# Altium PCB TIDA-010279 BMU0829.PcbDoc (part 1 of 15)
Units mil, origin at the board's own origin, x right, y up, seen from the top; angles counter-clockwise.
Board outline 11269.69 x 4438.98 mil, 4 copper layers (Top Layer, Signal Layer 1, Signal Layer 2, Bottom Layer), stack 61.6 mil thick; 1494 components, 725 nets, 3766 pads, 2728 vias.
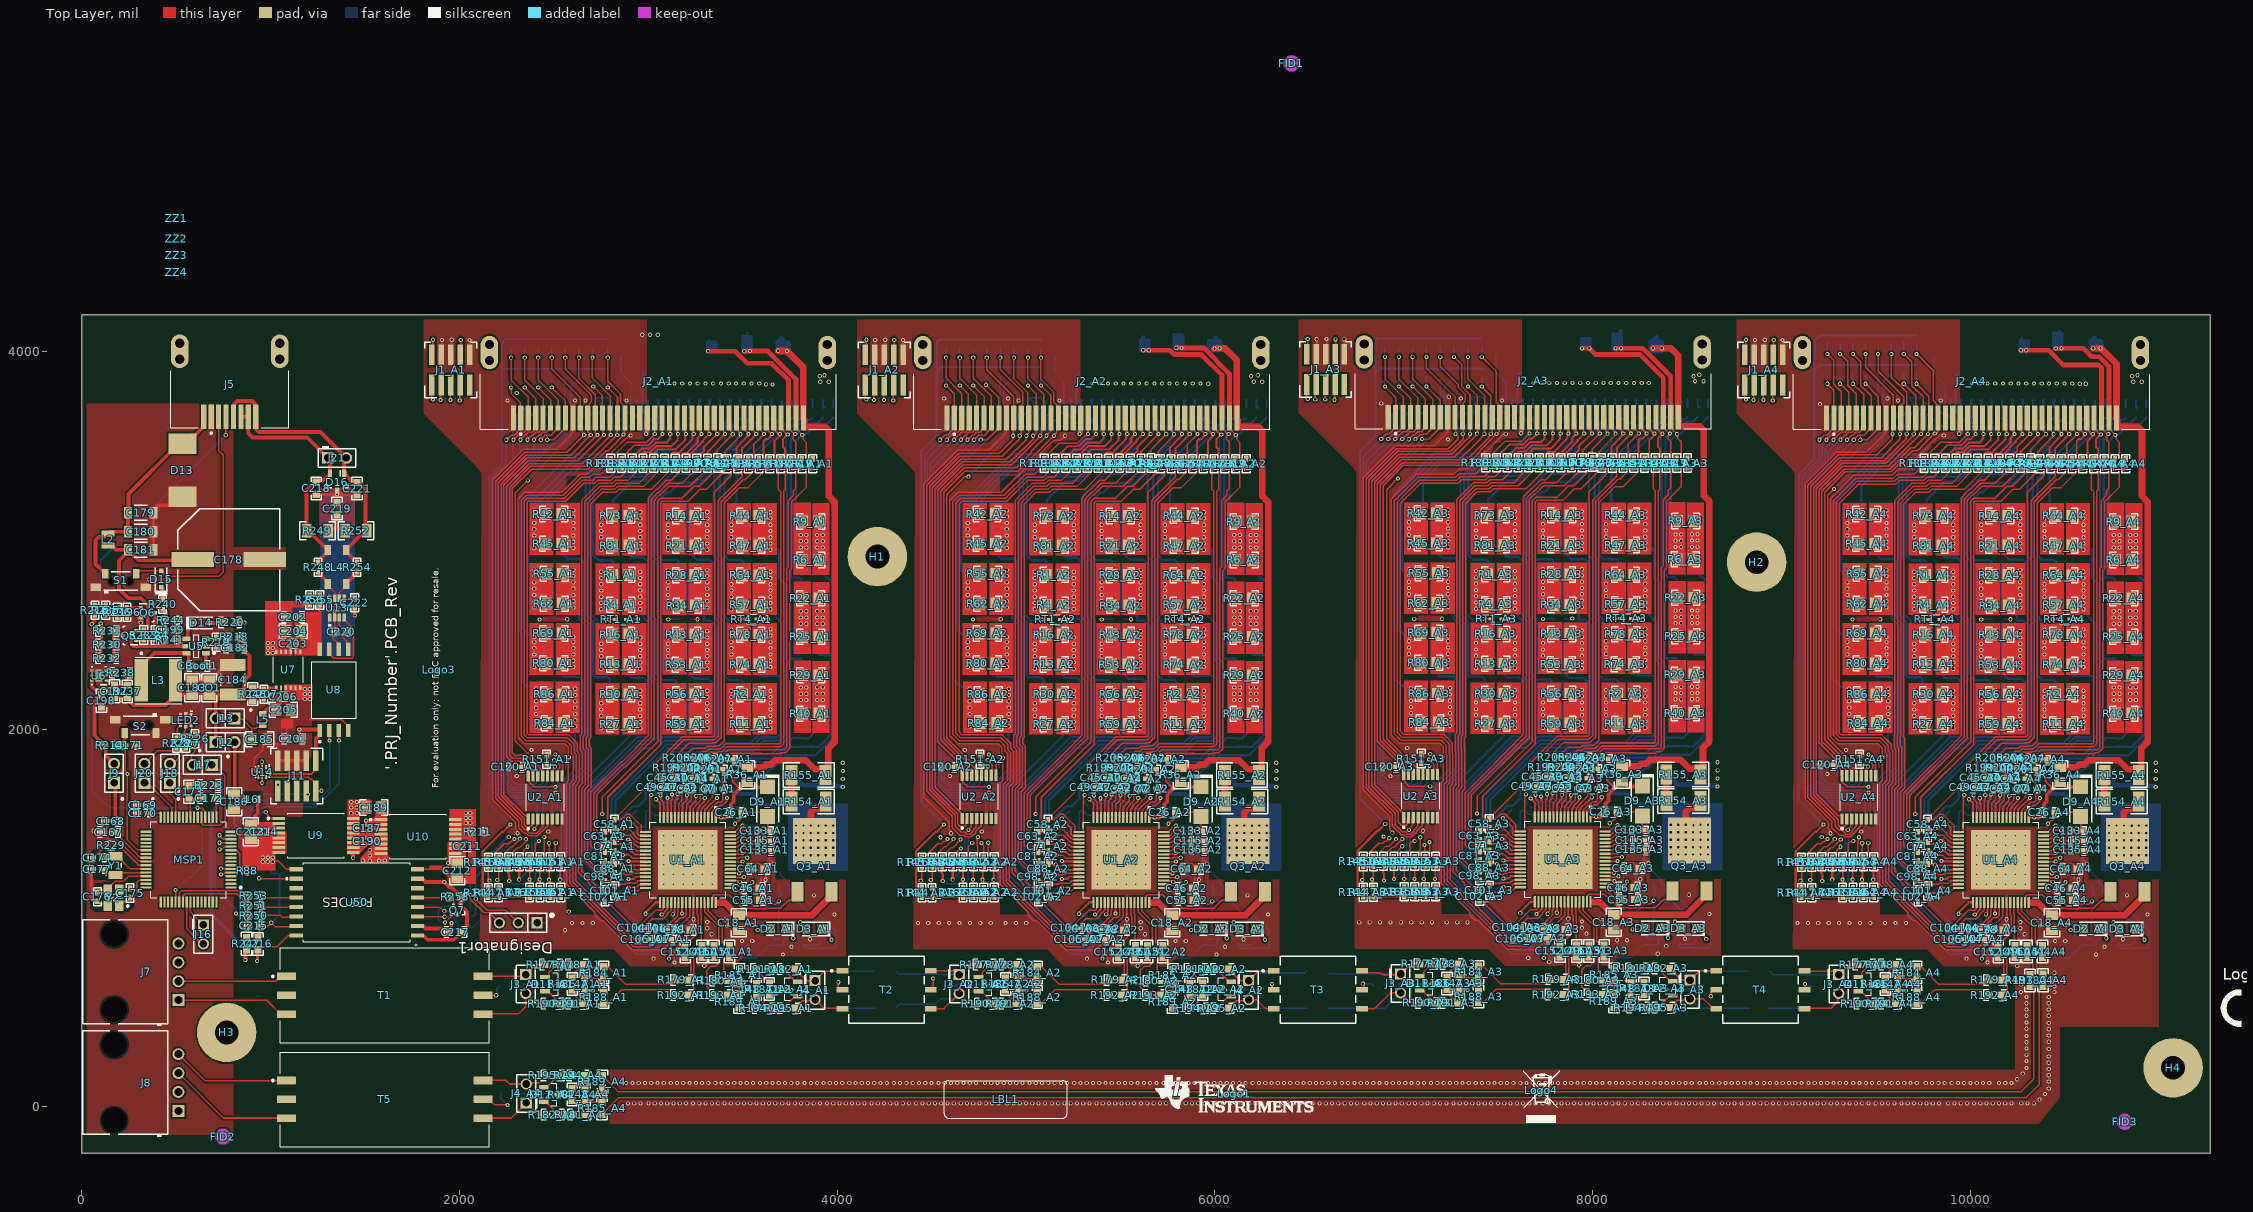
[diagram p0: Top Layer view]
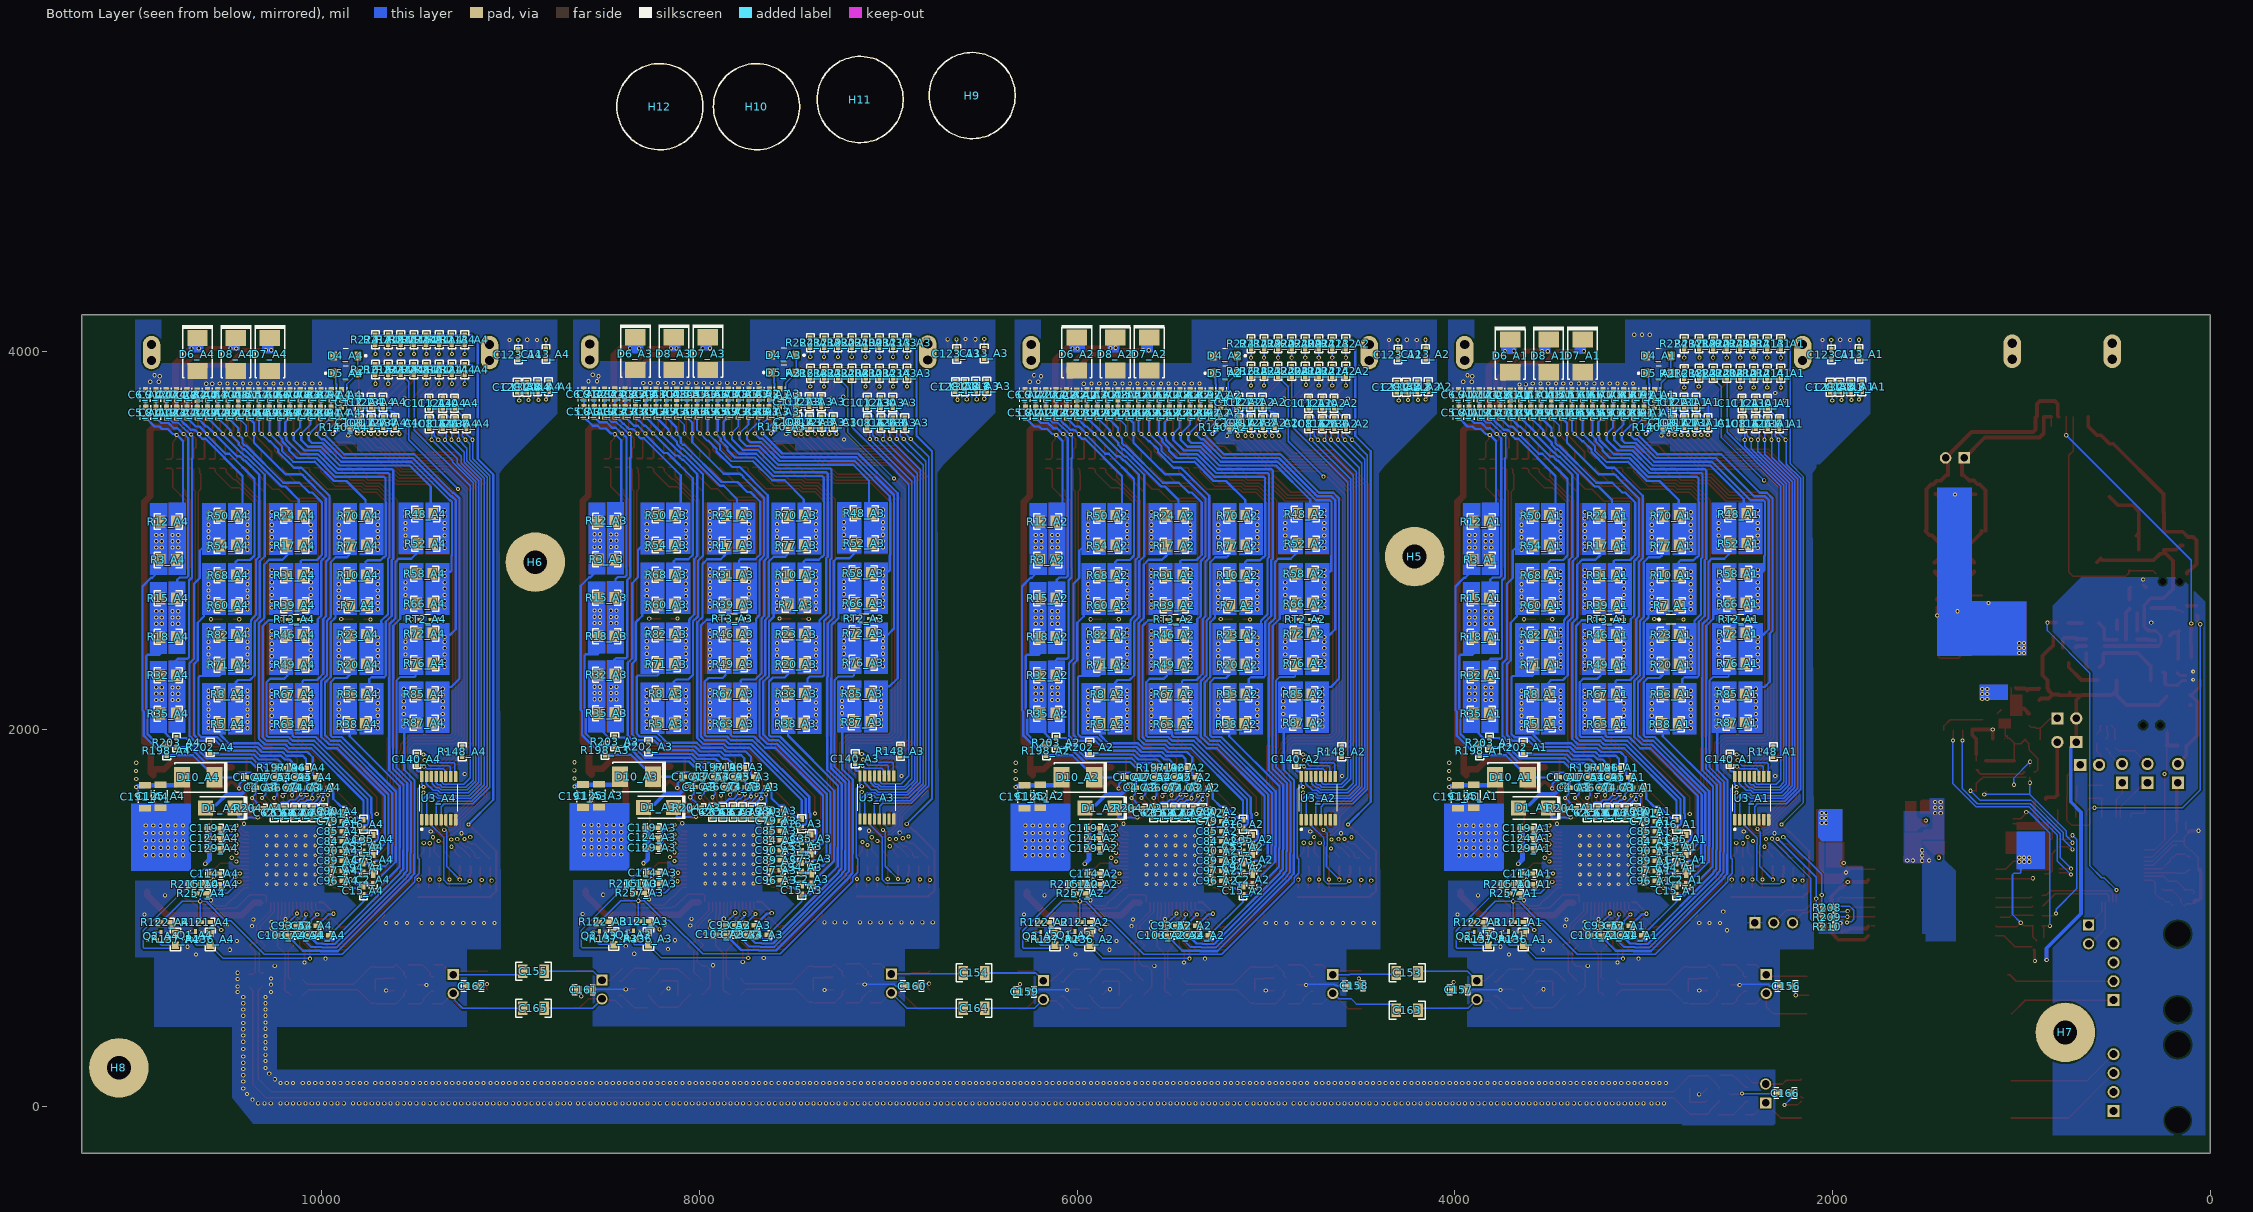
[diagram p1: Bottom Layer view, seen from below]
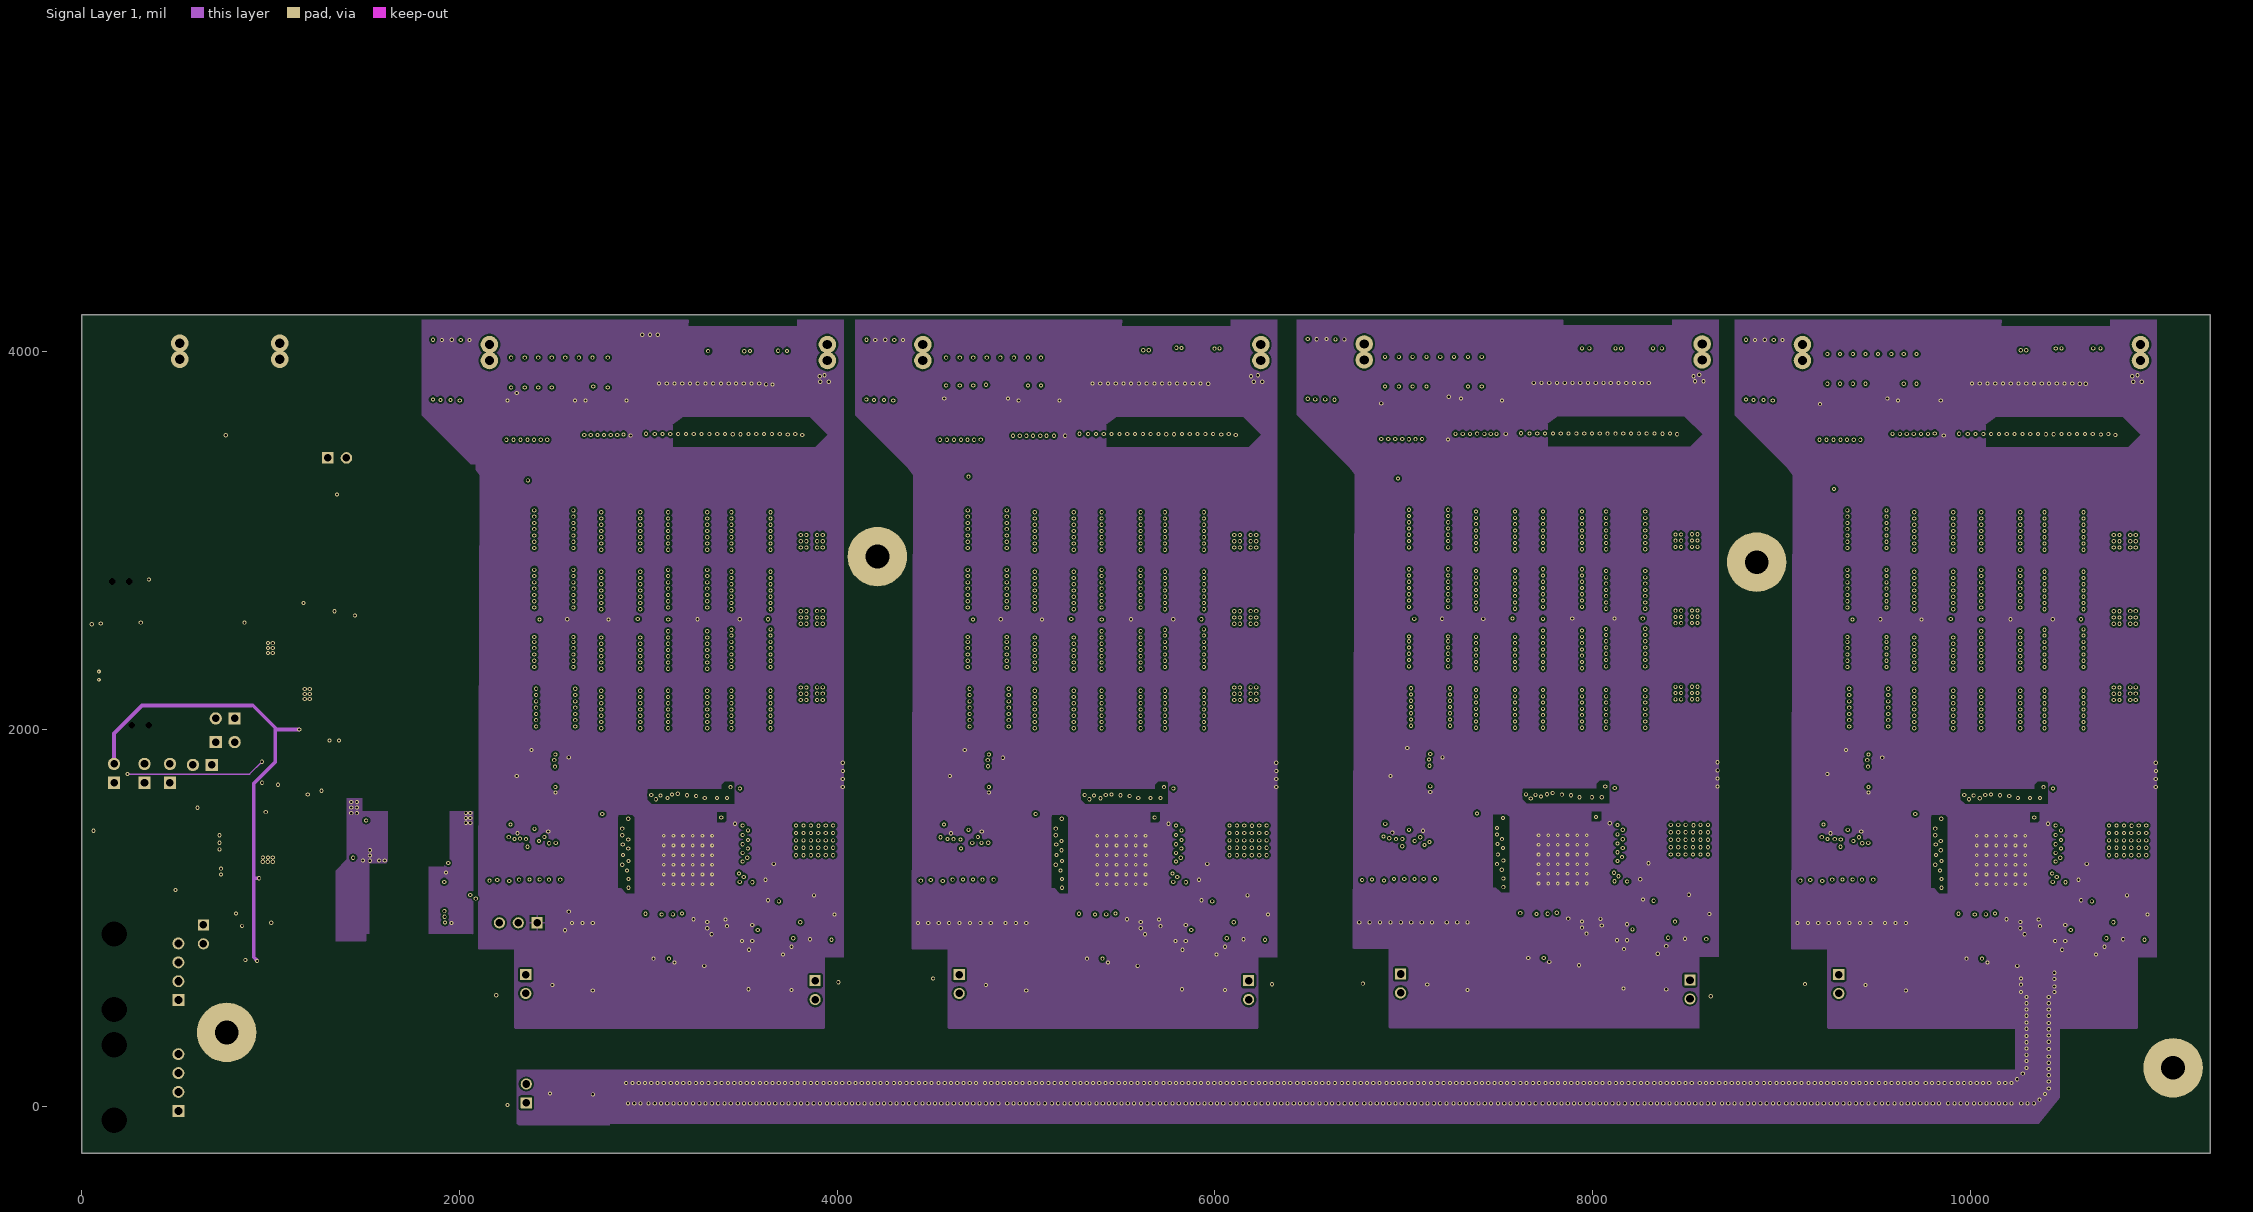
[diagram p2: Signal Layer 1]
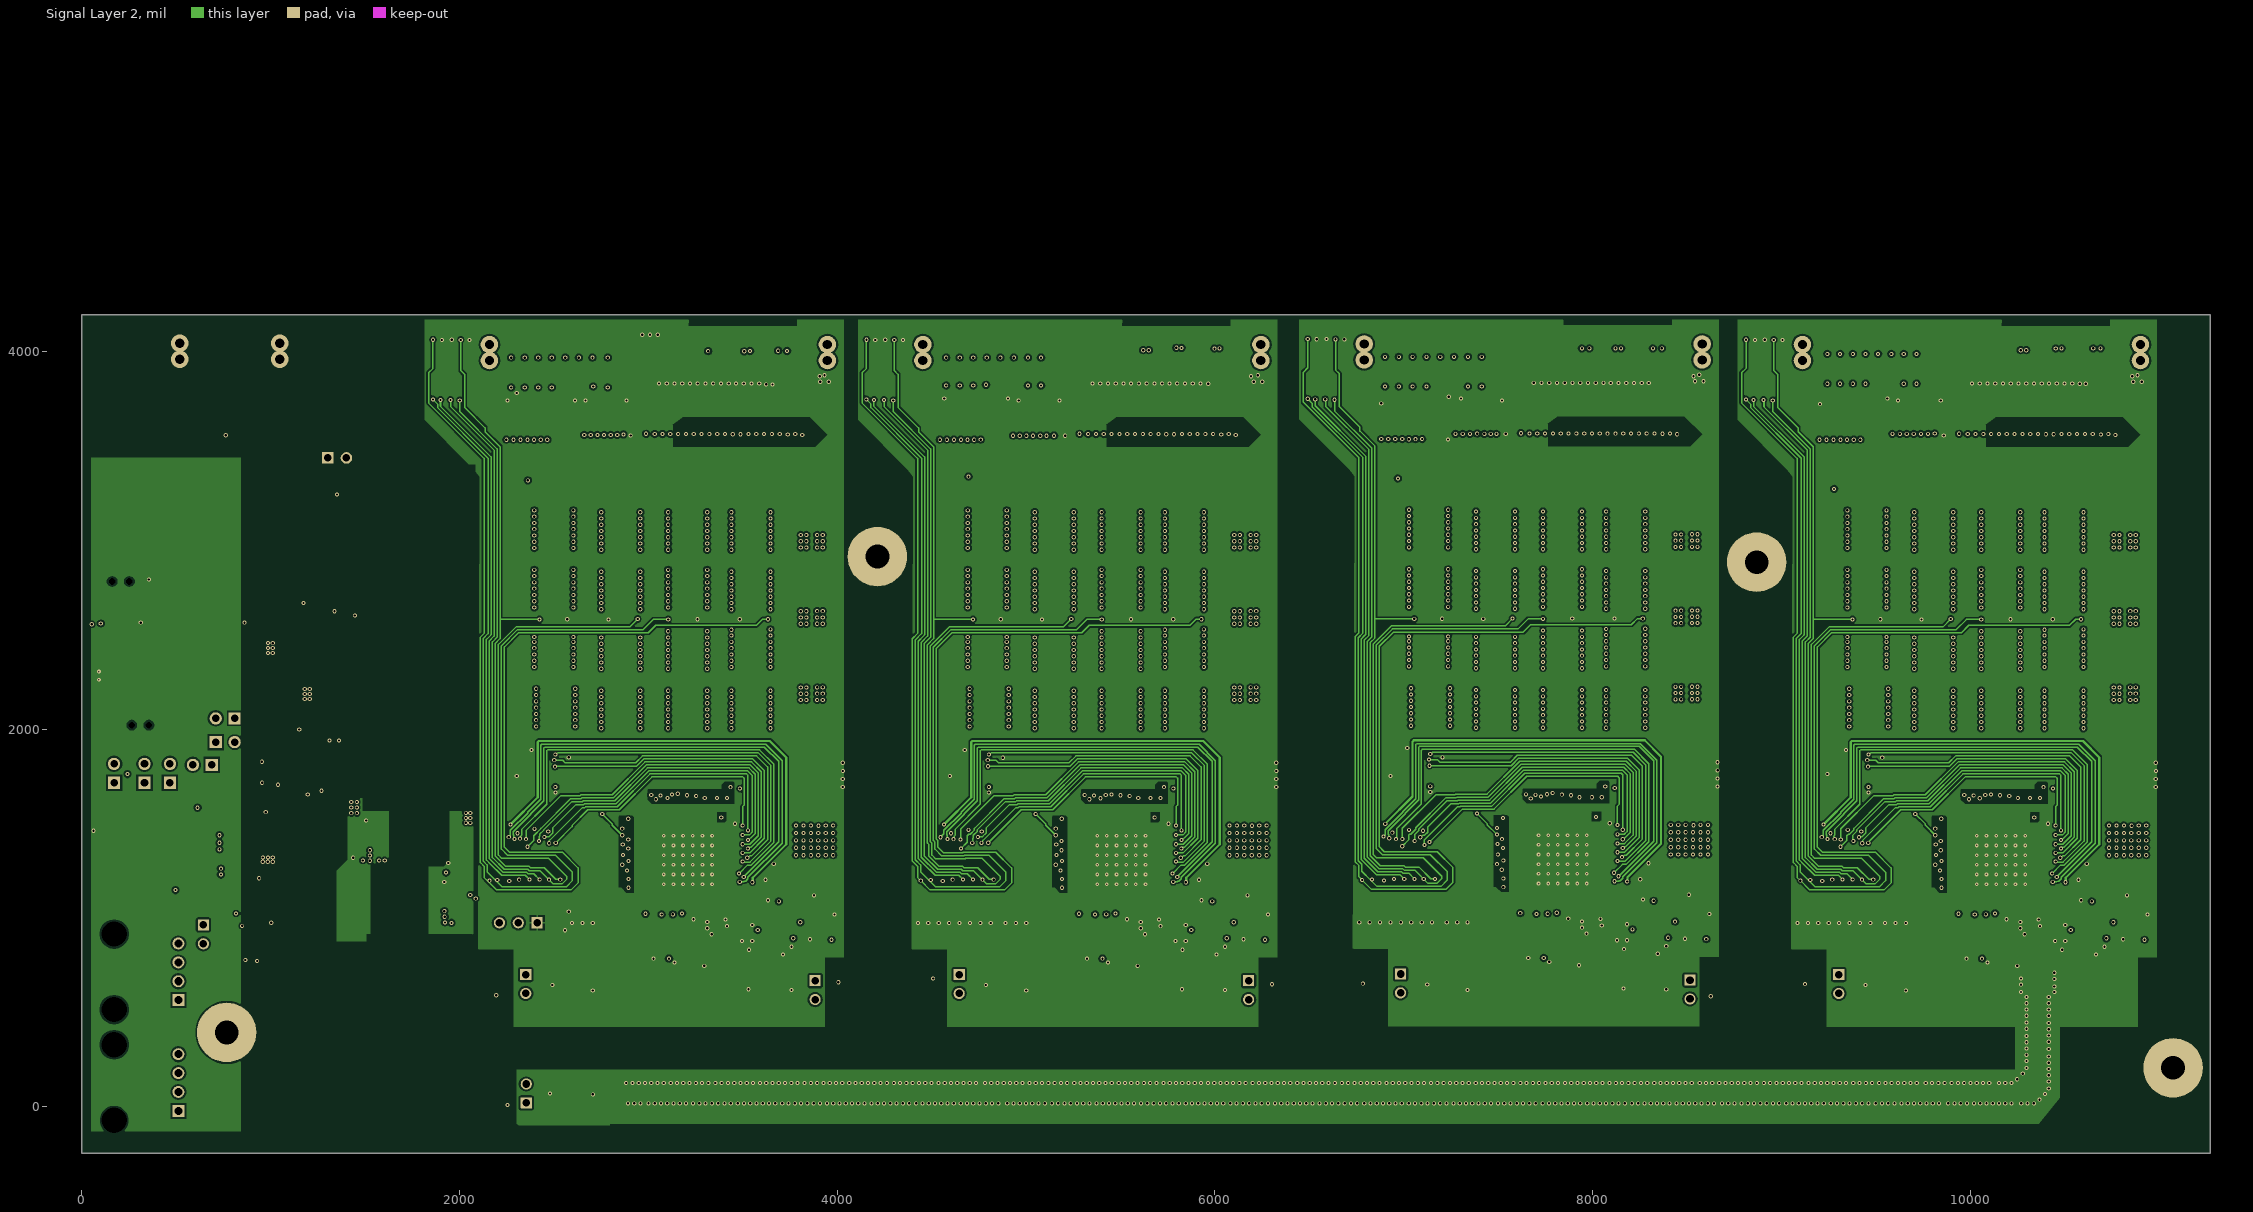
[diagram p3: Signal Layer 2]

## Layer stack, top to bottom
Top Solder: solder mask 0.4, Solder Resist, Dk 3.5
Top Layer: signal copper 2.8
Dielectric 1: prepreg 8, FR-4 High Tg, Dk 4.2
Signal Layer 1: signal copper 1.4
Dielectric 2: core 37.2, FR-4 High Tg, Dk 4.2
Signal Layer 2: signal copper 1.4
Dielectric 3: prepreg 8, FR-4 High Tg, Dk 4.2
Bottom Layer: signal copper 2.8
Bottom Solder: solder mask 0.4, Solder Resist, Dk 3.5

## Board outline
0,-246.06 11269.69,-246.06 11269.68,4192.91 0,4192.91

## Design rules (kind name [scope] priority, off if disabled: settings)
AcuteAngle [All] p1: minimum=4.50000000000000E+0001 checktracksonly=FALSE
AssemblyTestPointUsage [All] p1: valid=2
BoardOutlineClearance BoardOutlineClearance_MountingHoles [OnCopper and InComponentClass('Mounting Holes')] p1: gap=39.37 ignorepadtopadclearanceinfootprint=FALSE
BoardOutlineClearance BoardOutlineClearance_Poly [OnCopper and IsPoly] p2: gap=25 ignorepadtopadclearanceinfootprint=FALSE
BoardOutlineClearance [OnCopper and Not InComponentClass('Logo') and not InComponentClass('FiducialMark') and not InRegion(1000,500,4000,800) and not InPoly] p3: gap=40 ignorepadtopadclearanceinfootprint=FALSE
Clearance Clearance_Keepouts [((IsTrack Or IsArc) And Not InPoly) And IsFree and IsKeepOut vs ((IsTrack Or IsArc) And Not InPoly) And IsFree and IsKeepOut] p1: gap=0 ignorepadtopadclearanceinfootprint=FALSE
Clearance Clearance_Poly [InPolygon] p2: gap=10 ignorepadtopadclearanceinfootprint=TRUE
Clearance Clearance_FiducialMark [IsKeepOut and InComponentClass('FiducialMark') vs IsPad and InComponentClass('FiducialMark')] p3: gap=0 ignorepadtopadclearanceinfootprint=FALSE
Clearance [All] p4: gap=7.87 ignorepadtopadclearanceinfootprint=TRUE
ComponentClearance ComponentClearance_MountingHoles_FiducialMarks [InComponentClass('Mounting Holes') vs InComponentClass('FiducialMark')] p1: gap=50 collisioncheckmode=3 verticalgap=10 showdistances=FALSE
ComponentClearance ComponentClearance_Shunt [InComponentClass('Header') vs InComponentClass('Shunt')] p2: gap=0 collisioncheckmode=3 verticalgap=0 showdistances=FALSE
ComponentClearance ComponentClearance_Logo [InComponentClass('Logo')] p3: gap=30 collisioncheckmode=3 verticalgap=10 showdistances=FALSE
ComponentClearance ComponentClearance_ScrewToNut [(HasFootprint('NY PMS 440 0025 PH')) vs (HasFootprint('Keystone_1902C'))] p4: gap=5 collisioncheckmode=3 verticalgap=10 showdistances=FALSE
ComponentClearance ComponentClearance_MountingHoles [InComponentClass('Mounting Holes')] p5: gap=100 collisioncheckmode=3 verticalgap=100000 showdistances=FALSE
ComponentClearance ComponentClearance_SmallPassives [HasFootprint('0201*') or HasFootprint('0402*') or HasFootprint('0508') or HasFootprint('0603*') or HasFootprint('0612') or HasFootprint('0805*') or HasFootprint('0815*') or HasFootprint('0830*') or HasFootprint('1206*') or HasFootprint('1210*') or HasFootprint('1808*') or HasFootprint('1812*') or HasFootprint('1825*') or HasFootprint('2010*') or HasFootprint('2220*') or HasFootprint('2225*') or HasFootprint('2512*') or HasFootprint('2728*') or HasFootprint('3518*') vs HasFootprint('0201*') or HasFootprint('0402*') or HasFootprint('0508') or HasFootprint('0603*') or HasFootprint('0612') or HasFootprint('0805*') or HasFootprint('0815*') or HasFootprint('0830*') or HasFootprint('1206*') or HasFootprint('1210*') or HasFootprint('1808*') or HasFootprint('1812*') or HasFootprint('1825*') or HasFootprint('2010*') or HasFootprint('2220*') or HasFootprint('2225*') or HasFootprint('2512*') or HasFootprint('2728*') or HasFootprint('3518*')] p6: gap=14.96 collisioncheckmode=3 verticalgap=10 showdistances=FALSE
ComponentClearance ComponentClearance_THtoSMT [IsThruComponent vs IsSMTComponent] p7: gap=30 collisioncheckmode=3 verticalgap=30 showdistances=FALSE
ComponentClearance ComponentClearance_THtoTH [IsThruComponent vs IsThruComponent] p8: gap=20 collisioncheckmode=3 verticalgap=30 showdistances=FALSE
ComponentClearance [All] p9: gap=20 collisioncheckmode=3 verticalgap=10 showdistances=FALSE
DiffPairsRouting [All] p1: maxlimit=100 minlimit=10 mostfreqgap=10 toplayer_minwidth=15 toplayer_maxwidth=15 toplayer_prefwidth=15 midlayer1_minwidth=15 midlayer1_maxwidth=15 midlayer1_prefwidth=15 midlayer2_minwidth=15 midlayer2_maxwidth=15 midlayer2_prefwidth=15 bottomlayer_minwidth=15 bottomlayer_maxwidth=15 bottomlayer_prefwidth=15 maxuncoupledlength=1000
FabricationTestPointUsage TestPointUsage [All] p1: valid=2 allowmultiple=FALSE
FabricationTestpoint Testpoint [All] p1: side=3 testpointundercomponent=TRUE minsize=40 maxsize=100 preferedsize=60 minholesize=0 maxholesize=40 preferedholesize=32 testpointgrid=1 allowsidetop=TRUE allowsidebottom=TRUE usegrid=TRUE gridtolerance=0.01
FanoutControl Fanout_LCC [IsLCC] p1: bgadir=Out bgaviamode=Centered fanoutstyle=Auto fanoutdirection=Alternating viagrid=1 // Fanout_LCC (Default Rule)
FanoutControl Fanout_BGA [IsBGA] p2: bgadir=Out bgaviamode=Centered fanoutstyle=Auto fanoutdirection=Alternating viagrid=1 // Fanout_BGA (Default Rule)
FanoutControl Fanout_Default [All] p4: bgadir=Out bgaviamode=Centered fanoutstyle=Auto fanoutdirection=Alternating viagrid=1 // Fanout_Default (Default Rule)
FanoutControl Fanout_Small [(CompPinCount < 5)] p5: bgadir=Out bgaviamode=Centered fanoutstyle=Auto fanoutdirection=OutThenIn viagrid=1 // Fanout_Small (Default Rule)
HoleSize [All] p1: absolutevalues=TRUE maxlimit=251 minlimit=7.87 maxpercent=80.000 minpercent=20.000
MinimumAnnularRing MinimumAnnularRing_ThermalPadVias [IsVia and InAnyComponent] p1: minimumring=5.91
MinimumAnnularRing [All] p2: minimumring=5
MinimumSolderMaskSliver MinimumSolderMaskSliver_Logo [InComponentClass('Logo') vs InComponentClass('Logo')] p1: minsoldermaskwidth=0.7
MinimumSolderMaskSliver [All] p2: minsoldermaskwidth=3.94
PlaneConnect [All] p1: planeconnectstyle=Relief reliefexpansion=10 reliefentries=4 reliefconductorwidth=10 reliefairgap=10
PolygonConnect [All] p1: thpad.connectstyle=Relief thpad.reliefconductorwidth=10 thpad.reliefentries=4 thpad.polygonreliefangle="90 Angle" thpad.airgapwidth=10 smdpad.connectstyle=Direct smdpad.reliefconductorwidth=10 smdpad.reliefentries=4 smdpad.polygonreliefangle="90 Angle" smdpad.airgapwidth=10 via.connectstyle=Direct via.reliefconductorwidth=10 via.reliefentries=4 via.polygonreliefangle="90 Angle" via.airgapwidth=10
RoomDefinition [InComponentClass('Room Definition3')] p1: confinementstyle=ConfineIn formatcopy=TRUE lockcomponents=FALSE outline 1788.32,393.7 4074.8,393.7 4074.8,4320.87 1788.32,4320.87
RoomDefinition RoomDefinition_1 [InComponentClass('Room Definition6') vs False] p2: confinementstyle=ConfineIn formatcopy=TRUE lockcomponents=FALSE outline 4083.33,393.7 6369.82,393.7 6369.82,4320.87 4083.33,4320.87
RoomDefinition RoomDefinition_2 [InComponentClass('Room Definition7') vs False] p3: confinementstyle=ConfineIn formatcopy=TRUE lockcomponents=FALSE outline 6419.93,396.91 8706.42,396.91 8706.42,4324.07 6419.93,4324.07
RoomDefinition RoomDefinition_3 [InComponentClass('Room Definition8') vs False] p4 off: confinementstyle=ConfineIn formatcopy=TRUE lockcomponents=FALSE outline 8740.16,393.7 11026.65,393.7 11026.65,4320.87 8740.16,4320.87
RoutingVias ThermalPadVias [IsVia and InAnyComponent] p1: holewidth=7.87 width=19.68 viastyle="Through Hole" minholewidth=7.87 minwidth=19.68 maxholewidth=50 maxwidth=93
RoutingVias [All] p2: holewidth=16 width=34 viastyle="Through Hole" minholewidth=7.8 minwidth=22 maxholewidth=50 maxwidth=93
SilkToBoardRegionClearance [Not ((IsComment or IsDesignator) And (Hide <> 'False')) and not InRegion(1000,500,4000,800)] p1:
SilkToSilkClearance SilkToSilkClearance_Pb-FreeLogo [(HasFootprint('Pb-Free_Overlay_Medium') OR HasFootprint('Pb-Free_Overlay_Small')) vs (HasFootprint('Pb-Free_Overlay_Medium') OR HasFootprint('Pb-Free_Overlay_Small'))] p1: silktosilkclearance=0
SilkToSilkClearance [All] p2: silktosilkclearance=3.94
SilkToSolderMaskClearance SilkToComponentPadClearance [(IsPad or IsFill or IsRegion) and InAnycomponent] p1: minsilkscreentomaskgap=3 clearancetoexposedcopper=TRUE
SilkToSolderMaskClearance "Silk to Solder Mask Opening" [All] p2: minsilkscreentomaskgap=3.94 clearancetoexposedcopper=FALSE
SolderMaskExpansion [All] p1: expansion=1.97 istentingtop=FALSE
UnRoutedNet [All] p1: checkbadconnections=TRUE
Width [All] p1: maxlimit=100 minlimit=6 preferedwidth=8 checkconnectedcopper=TRUE
14 further rules are at their usual default settings.

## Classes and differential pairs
component class MCU0: C167 C168 C169 C170 C171 C172 C173 C174 C175 C176 C177 C178 C179 C180 C181 C182 C183 C184 C185 C186 C187 C189 C190 C196 C197 C198 C199 C201 C202 C203 C204 C205 C206 C207 C211 C212 C213 C214 C215 C216 C217 C218 C219 C220 C221 C222 CBoot1 CO1 D13 D14 D15 D16 J9 J11 J12 J13 J16 J17 J18 J20 J21 L2 L3 L4 L5 L6 LED2 MSP1 Q5 Q6 Q7 R88 R214 R216 R218 R219 R220 R223 R226 R227 R228 R229 R230 R231 R232 R233 R234 R235 R236 R237 R238 R240 R241 R244 R246 R247 R248 R249 R250 R251 R252 R253 R254 R255 R256 R258 S2 U5 U6 U7 U8 U9 U10 U13 U14 U50 Y1 Y2
component class Header: J3_A1 J3_A2 J3_A3 J3_A4 J4_A1 J4_A2 J4_A3 J4_A4 J9 J12 J13 J16 J17 J18 J20
component class "Mounting Holes": H1 H2 H3 H4
component class Logo: Logo1
component class FiducialMark: FID1 FID2 FID3
component class AssemblyNote: ZZ1 ZZ2 ZZ3 ZZ4
component class Label: LBL1

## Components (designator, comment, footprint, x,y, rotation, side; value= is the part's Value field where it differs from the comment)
C1_A1 "GCM155R71H104KE02D" 0402 3421.64,1744.01 r0 bottom value=0.1uF (schematic designator C1)
C1_A2 "GCM155R71H104KE02D" 0402 5716.65,1744.01 r0 bottom value=0.1uF (schematic designator C1)
C1_A3 "GCM155R71H104KE02D" 0402 8053.25,1747.22 r0 bottom value=0.1uF (schematic designator C1)
C1_A4 "GCM155R71H104KE02D" 0402 10373.48,1744.01 r0 bottom value=0.1uF (schematic designator C1)
C2_A1 "GCM155R71H104KE02D" 0402 2773.73,1202.94 r270 bottom value=0.1uF (schematic designator C2)
C2_A2 "GCM155R71H104KE02D" 0402 5068.74,1202.94 r270 bottom value=0.1uF (schematic designator C2)
C2_A3 "GCM155R71H104KE02D" 0402 7405.34,1206.15 r270 bottom value=0.1uF (schematic designator C2)
C2_A4 "GCM155R71H104KE02D" 0402 9725.57,1202.94 r270 bottom value=0.1uF (schematic designator C2)
C3_A1 "GCM155R71H104KE02D" 0402 3036.13,1690.14 r180 bottom value=0.1uF (schematic designator C3)
C3_A2 "GCM155R71H104KE02D" 0402 5331.15,1690.14 r180 bottom value=0.1uF (schematic designator C3)
C3_A3 "GCM155R71H104KE02D" 0402 7667.74,1693.35 r180 bottom value=0.1uF (schematic designator C3)
C3_A4 "GCM155R71H104KE02D" 0402 9987.97,1690.14 r180 bottom value=0.1uF (schematic designator C3)
C4_A1 "GCM155R71H104KE02D" 0402 3367,1690.14 r180 bottom value=0.1uF (schematic designator C4)
C4_A2 "GCM155R71H104KE02D" 0402 5662.01,1690.14 r180 bottom value=0.1uF (schematic designator C4)
C4_A3 "GCM155R71H104KE02D" 0402 7998.61,1693.35 r180 bottom value=0.1uF (schematic designator C4)
C4_A4 "GCM155R71H104KE02D" 0402 10318.84,1690.14 r180 bottom value=0.1uF (schematic designator C4)
C5_A1 "CGA3E2X7R2A223K080AA" FP-CGA3E2X7R2A223K080AA_0603-MFG 3978.41,3676.14 r90 bottom value=22nF (schematic designator C5)
C5_A2 "CGA3E2X7R2A223K080AA" FP-CGA3E2X7R2A223K080AA_0603-MFG 6273.43,3676.14 r90 bottom value=22nF (schematic designator C5)
C5_A3 "CGA3E2X7R2A223K080AA" FP-CGA3E2X7R2A223K080AA_0603-MFG 8610.03,3679.34 r90 bottom value=22nF (schematic designator C5)
C5_A4 "CGA3E2X7R2A223K080AA" FP-CGA3E2X7R2A223K080AA_0603-MFG 10930.26,3676.14 r90 bottom value=22nF (schematic designator C5)
C6_A1 "CGA3E2X7R2A223K080AA" FP-CGA3E2X7R2A223K080AA_0603-MFG 3979.76,3769.17 r90 bottom value=22nF (schematic designator C6)
C6_A2 "CGA3E2X7R2A223K080AA" FP-CGA3E2X7R2A223K080AA_0603-MFG 6274.77,3769.17 r90 bottom value=22nF (schematic designator C6)
C6_A3 "CGA3E2X7R2A223K080AA" FP-CGA3E2X7R2A223K080AA_0603-MFG 8611.37,3772.38 r90 bottom value=22nF (schematic designator C6)
C6_A4 "CGA3E2X7R2A223K080AA" FP-CGA3E2X7R2A223K080AA_0603-MFG 10931.6,3769.17 r90 bottom value=22nF (schematic designator C6)
C7_A1 "GCM155R71H472KA37D" 0402 3370.1,1683.55 r180 top value=4700pF (schematic designator C7)
C7_A2 "GCM155R71H472KA37D" 0402 5665.11,1683.55 r180 top value=4700pF (schematic designator C7)
C7_A3 "GCM155R71H472KA37D" 0402 8001.71,1686.76 r180 top value=4700pF (schematic designator C7)
C7_A4 "GCM155R71H472KA37D" 0402 10321.94,1683.55 r180 top value=4700pF (schematic designator C7)
C8_A1 "CGA3E2X7R2A223K080AA" FP-CGA3E2X7R2A223K080AA_0603-MFG 3923.98,3676.14 r90 bottom value=22nF (schematic designator C8)
C8_A2 "CGA3E2X7R2A223K080AA" FP-CGA3E2X7R2A223K080AA_0603-MFG 6219,3676.14 r90 bottom value=22nF (schematic designator C8)
C8_A3 "CGA3E2X7R2A223K080AA" FP-CGA3E2X7R2A223K080AA_0603-MFG 8555.6,3679.34 r90 bottom value=22nF (schematic designator C8)
C8_A4 "CGA3E2X7R2A223K080AA" FP-CGA3E2X7R2A223K080AA_0603-MFG 10875.83,3676.14 r90 bottom value=22nF (schematic designator C8)
C9_A1 "CGA3E2X7R2A223K080AA" FP-CGA3E2X7R2A223K080AA_0603-MFG 3925.12,3769.17 r90 bottom value=22nF (schematic designator C9)
C9_A2 "CGA3E2X7R2A223K080AA" FP-CGA3E2X7R2A223K080AA_0603-MFG 6220.14,3769.17 r90 bottom value=22nF (schematic designator C9)
C9_A3 "CGA3E2X7R2A223K080AA" FP-CGA3E2X7R2A223K080AA_0603-MFG 8556.73,3772.38 r90 bottom value=22nF (schematic designator C9)
C9_A4 "CGA3E2X7R2A223K080AA" FP-CGA3E2X7R2A223K080AA_0603-MFG 10876.96,3769.17 r90 bottom value=22nF (schematic designator C9)
C11_A1 "CGA3E2X7R2A223K080AA" FP-CGA3E2X7R2A223K080AA_0603-MFG 3869.55,3676.14 r90 bottom value=22nF (schematic designator C11)
C11_A2 "CGA3E2X7R2A223K080AA" FP-CGA3E2X7R2A223K080AA_0603-MFG 6164.57,3676.14 r90 bottom value=22nF (schematic designator C11)
C11_A3 "CGA3E2X7R2A223K080AA" FP-CGA3E2X7R2A223K080AA_0603-MFG 8501.17,3679.34 r90 bottom value=22nF (schematic designator C11)
C11_A4 "CGA3E2X7R2A223K080AA" FP-CGA3E2X7R2A223K080AA_0603-MFG 10821.4,3676.14 r90 bottom value=22nF (schematic designator C11)
C12_A1 "CGA3E2X7R2A223K080AA" FP-CGA3E2X7R2A223K080AA_0603-MFG 3870.49,3769.17 r90 bottom value=22nF (schematic designator C12)
C12_A2 "CGA3E2X7R2A223K080AA" FP-CGA3E2X7R2A223K080AA_0603-MFG 6165.5,3769.17 r90 bottom value=22nF (schematic designator C12)
C12_A3 "CGA3E2X7R2A223K080AA" FP-CGA3E2X7R2A223K080AA_0603-MFG 8502.1,3772.38 r90 bottom value=22nF (schematic designator C12)
C12_A4 "CGA3E2X7R2A223K080AA" FP-CGA3E2X7R2A223K080AA_0603-MFG 10822.33,3769.17 r90 bottom value=22nF (schematic designator C12)
C14_A1 "GCM155R71H472KA37D" 0402 3316.8,1737.08 r180 top value=4700pF (schematic designator C14)
C14_A2 "GCM155R71H472KA37D" 0402 5611.81,1737.08 r180 top value=4700pF (schematic designator C14)
C14_A3 "GCM155R71H472KA37D" 0402 7948.41,1740.29 r180 top value=4700pF (schematic designator C14)
C14_A4 "GCM155R71H472KA37D" 0402 10268.64,1737.08 r180 top value=4700pF (schematic designator C14)
C15_A1 "GCM155R71H104KE02D" 0402 2826.12,1144.09 r270 bottom value=0.1uF (schematic designator C15)
C15_A2 "GCM155R71H104KE02D" 0402 5121.14,1144.09 r270 bottom value=0.1uF (schematic designator C15)
C15_A3 "GCM155R71H104KE02D" 0402 7457.73,1147.3 r270 bottom value=0.1uF (schematic designator C15)
C15_A4 "GCM155R71H104KE02D" 0402 9777.96,1144.09 r270 bottom value=0.1uF (schematic designator C15)
C16_A1 "GCM155R71H104KE02D" 0402 2826.12,1496.42 r270 bottom value=0.1uF (schematic designator C16)
C16_A2 "GCM155R71H104KE02D" 0402 5121.14,1496.42 r270 bottom value=0.1uF (schematic designator C16)
C16_A3 "GCM155R71H104KE02D" 0402 7457.73,1499.63 r270 bottom value=0.1uF (schematic designator C16)
C16_A4 "GCM155R71H104KE02D" 0402 9777.96,1496.42 r270 bottom value=0.1uF (schematic designator C16)
C17_A1 "GCM155R71H104KE02D" 0402 3314.73,1744.01 r180 bottom value=0.1uF (schematic designator C17)
C17_A2 "GCM155R71H104KE02D" 0402 5609.75,1744.01 r180 bottom value=0.1uF (schematic designator C17)
C17_A3 "GCM155R71H104KE02D" 0402 7946.34,1747.21 r180 bottom value=0.1uF (schematic designator C17)
C17_A4 "GCM155R71H104KE02D" 0402 10266.57,1744.01 r180 bottom value=0.1uF (schematic designator C17)
C18_A1 "C0805C475J8RACAUTO" 0805_HV 3479.51,973.59 r90 top value=4.7uF (schematic designator C18)
C18_A2 "C0805C475J8RACAUTO" 0805_HV 5774.52,973.59 r90 top value=4.7uF (schematic designator C18)
C18_A3 "C0805C475J8RACAUTO" 0805_HV 8111.12,976.79 r90 top value=4.7uF (schematic designator C18)
C18_A4 "C0805C475J8RACAUTO" 0805_HV 10431.35,973.59 r90 top value=4.7uF (schematic designator C18)
C19_A1 "CGA3E2X7R2A223K080AA" FP-CGA3E2X7R2A223K080AA_0603-MFG 3815.12,3676.14 r90 bottom value=22nF (schematic designator C19)
C19_A2 "CGA3E2X7R2A223K080AA" FP-CGA3E2X7R2A223K080AA_0603-MFG 6110.14,3676.14 r90 bottom value=22nF (schematic designator C19)
C19_A3 "CGA3E2X7R2A223K080AA" FP-CGA3E2X7R2A223K080AA_0603-MFG 8446.74,3679.34 r90 bottom value=22nF (schematic designator C19)
C19_A4 "CGA3E2X7R2A223K080AA" FP-CGA3E2X7R2A223K080AA_0603-MFG 10766.97,3676.14 r90 bottom value=22nF (schematic designator C19)
C20_A1 "CGA3E2X7R2A223K080AA" FP-CGA3E2X7R2A223K080AA_0603-MFG 3815.85,3769.17 r90 bottom value=22nF (schematic designator C20)
C20_A2 "CGA3E2X7R2A223K080AA" FP-CGA3E2X7R2A223K080AA_0603-MFG 6110.87,3769.17 r90 bottom value=22nF (schematic designator C20)
C20_A3 "CGA3E2X7R2A223K080AA" FP-CGA3E2X7R2A223K080AA_0603-MFG 8447.46,3772.38 r90 bottom value=22nF (schematic designator C20)
C20_A4 "CGA3E2X7R2A223K080AA" FP-CGA3E2X7R2A223K080AA_0603-MFG 10767.69,3769.17 r90 bottom value=22nF (schematic designator C20)
C22_A1 "GCM155R71H472KA37D" 0402 3261.9,1683.78 r180 top value=4700pF (schematic designator C22)
C22_A2 "GCM155R71H472KA37D" 0402 5556.91,1683.78 r180 top value=4700pF (schematic designator C22)
C22_A3 "GCM155R71H472KA37D" 0402 7893.51,1686.99 r180 top value=4700pF (schematic designator C22)
C22_A4 "GCM155R71H472KA37D" 0402 10213.74,1683.78 r180 top value=4700pF (schematic designator C22)
C23_A1 "CGA3E2X7R2A223K080AA" FP-CGA3E2X7R2A223K080AA_0603-MFG 3760.69,3676.14 r90 bottom value=22nF (schematic designator C23)
C23_A2 "CGA3E2X7R2A223K080AA" FP-CGA3E2X7R2A223K080AA_0603-MFG 6055.71,3676.14 r90 bottom value=22nF (schematic designator C23)
C23_A3 "CGA3E2X7R2A223K080AA" FP-CGA3E2X7R2A223K080AA_0603-MFG 8392.31,3679.34 r90 bottom value=22nF (schematic designator C23)
C23_A4 "CGA3E2X7R2A223K080AA" FP-CGA3E2X7R2A223K080AA_0603-MFG 10712.54,3676.14 r90 bottom value=22nF (schematic designator C23)
C24_A1 "CGA3E2X7R2A223K080AA" FP-CGA3E2X7R2A223K080AA_0603-MFG 3761.22,3769.17 r90 bottom value=22nF (schematic designator C24)
C24_A2 "CGA3E2X7R2A223K080AA" FP-CGA3E2X7R2A223K080AA_0603-MFG 6056.23,3769.17 r90 bottom value=22nF (schematic designator C24)
C24_A3 "CGA3E2X7R2A223K080AA" FP-CGA3E2X7R2A223K080AA_0603-MFG 8392.83,3772.38 r90 bottom value=22nF (schematic designator C24)
C24_A4 "CGA3E2X7R2A223K080AA" FP-CGA3E2X7R2A223K080AA_0603-MFG 10713.06,3769.17 r90 bottom value=22nF (schematic designator C24)
C26_A1 "GCM188R72A103KA37J" 0603_HV 3464.28,1558.6 r180 top value=0.01uF (schematic designator C26)
C26_A2 "GCM188R72A103KA37J" 0603_HV 5759.3,1558.6 r180 top value=0.01uF (schematic designator C26)
C26_A3 "GCM188R72A103KA37J" 0603_HV 8095.9,1561.81 r180 top value=0.01uF (schematic designator C26)
C26_A4 "GCM188R72A103KA37J" 0603_HV 10416.12,1558.6 r180 top value=0.01uF (schematic designator C26)
C27_A1 "CGA3E2X7R2A223K080AA" FP-CGA3E2X7R2A223K080AA_0603-MFG 3706.26,3676.14 r90 bottom value=22nF (schematic designator C27)
C27_A2 "CGA3E2X7R2A223K080AA" FP-CGA3E2X7R2A223K080AA_0603-MFG 6001.28,3676.14 r90 bottom value=22nF (schematic designator C27)
C27_A3 "CGA3E2X7R2A223K080AA" FP-CGA3E2X7R2A223K080AA_0603-MFG 8337.88,3679.34 r90 bottom value=22nF (schematic designator C27)
C27_A4 "CGA3E2X7R2A223K080AA" FP-CGA3E2X7R2A223K080AA_0603-MFG 10658.11,3676.14 r90 bottom value=22nF (schematic designator C27)
C28_A1 "CGA3E2X7R2A223K080AA" FP-CGA3E2X7R2A223K080AA_0603-MFG 3706.58,3767.2 r90 bottom value=22nF (schematic designator C28)
C28_A2 "CGA3E2X7R2A223K080AA" FP-CGA3E2X7R2A223K080AA_0603-MFG 6001.6,3767.2 r90 bottom value=22nF (schematic designator C28)
C28_A3 "CGA3E2X7R2A223K080AA" FP-CGA3E2X7R2A223K080AA_0603-MFG 8338.19,3770.41 r90 bottom value=22nF (schematic designator C28)
C28_A4 "CGA3E2X7R2A223K080AA" FP-CGA3E2X7R2A223K080AA_0603-MFG 10658.42,3767.2 r90 bottom value=22nF (schematic designator C28)
C30_A1 "GCM155R71H472KA37D" 0402 3210.07,1743.6 r180 top value=4700pF (schematic designator C30)
C30_A2 "GCM155R71H472KA37D" 0402 5505.09,1743.6 r180 top value=4700pF (schematic designator C30)
C30_A3 "GCM155R71H472KA37D" 0402 7841.68,1746.8 r180 top value=4700pF (schematic designator C30)
C30_A4 "GCM155R71H472KA37D" 0402 10161.91,1743.6 r180 top value=4700pF (schematic designator C30)
C31_A1 "CGA3E2X7R2A223K080AA" FP-CGA3E2X7R2A223K080AA_0603-MFG 3651.83,3676.14 r90 bottom value=22nF (schematic designator C31)
C31_A2 "CGA3E2X7R2A223K080AA" FP-CGA3E2X7R2A223K080AA_0603-MFG 5946.85,3676.14 r90 bottom value=22nF (schematic designator C31)
C31_A3 "CGA3E2X7R2A223K080AA" FP-CGA3E2X7R2A223K080AA_0603-MFG 8283.44,3679.34 r90 bottom value=22nF (schematic designator C31)
C31_A4 "CGA3E2X7R2A223K080AA" FP-CGA3E2X7R2A223K080AA_0603-MFG 10603.67,3676.14 r90 bottom value=22nF (schematic designator C31)
C32_A1 "CGA3E2X7R2A223K080AA" FP-CGA3E2X7R2A223K080AA_0603-MFG 3651.95,3769.17 r90 bottom value=22nF (schematic designator C32)
C32_A2 "CGA3E2X7R2A223K080AA" FP-CGA3E2X7R2A223K080AA_0603-MFG 5946.96,3769.17 r90 bottom value=22nF (schematic designator C32)
C32_A3 "CGA3E2X7R2A223K080AA" FP-CGA3E2X7R2A223K080AA_0603-MFG 8283.56,3772.38 r90 bottom value=22nF (schematic designator C32)
C32_A4 "CGA3E2X7R2A223K080AA" FP-CGA3E2X7R2A223K080AA_0603-MFG 10603.79,3769.17 r90 bottom value=22nF (schematic designator C32)
C34_A1 "GCM155R71H104KE02D" 0402 3031.59,907.69 r0 bottom value=0.1uF (schematic designator C34)
C34_A2 "GCM155R71H104KE02D" 0402 5326.61,907.69 r0 bottom value=0.1uF (schematic designator C34)
C34_A3 "GCM155R71H104KE02D" 0402 7663.2,910.9 r0 bottom value=0.1uF (schematic designator C34)
C34_A4 "GCM155R71H104KE02D" 0402 9983.43,907.69 r0 bottom value=0.1uF (schematic designator C34)
C35_A1 "GCM155R71H104KE02D" 0402 2774.41,1415.92 r270 bottom value=0.1uF (schematic designator C35)
C35_A2 "GCM155R71H104KE02D" 0402 5069.43,1415.92 r270 bottom value=0.1uF (schematic designator C35)
C35_A3 "GCM155R71H104KE02D" 0402 7406.02,1419.13 r270 bottom value=0.1uF (schematic designator C35)
C35_A4 "GCM155R71H104KE02D" 0402 9726.25,1415.92 r270 bottom value=0.1uF (schematic designator C35)
C36_A1 "GCM155R71H104KE02D" 0402 3260.19,1690.24 r180 bottom value=0.1uF (schematic designator C36)
C36_A2 "GCM155R71H104KE02D" 0402 5555.21,1690.24 r180 bottom value=0.1uF (schematic designator C36)
C36_A3 "GCM155R71H104KE02D" 0402 7891.8,1693.45 r180 bottom value=0.1uF (schematic designator C36)
C36_A4 "GCM155R71H104KE02D" 0402 10212.03,1690.24 r180 bottom value=0.1uF (schematic designator C36)
C37_A1 "GCM155R71H472KA37D" 0402 3154.59,1693.04 r180 top value=4700pF (schematic designator C37)
C37_A2 "GCM155R71H472KA37D" 0402 5449.6,1693.04 r180 top value=4700pF (schematic designator C37)
C37_A3 "GCM155R71H472KA37D" 0402 7786.2,1696.25 r180 top value=4700pF (schematic designator C37)
C37_A4 "GCM155R71H472KA37D" 0402 10106.43,1693.04 r180 top value=4700pF (schematic designator C37)
C38_A1 "GCM188R71C105KA64D" 0603 3190.84,936.51 r180 top value=1uF (schematic designator C38)
C38_A2 "GCM188R71C105KA64D" 0603 5485.86,936.51 r180 top value=1uF (schematic designator C38)
C38_A3 "GCM188R71C105KA64D" 0603 7822.46,939.71 r180 top value=1uF (schematic designator C38)
C38_A4 "GCM188R71C105KA64D" 0603 10142.69,936.51 r180 top value=1uF (schematic designator C38)
C39_A1 "CGA3E2X7R2A223K080AA" FP-CGA3E2X7R2A223K080AA_0603-MFG 3597.4,3676.14 r90 bottom value=22nF (schematic designator C39)
C39_A2 "CGA3E2X7R2A223K080AA" FP-CGA3E2X7R2A223K080AA_0603-MFG 5892.42,3676.14 r90 bottom value=22nF (schematic designator C39)
C39_A3 "CGA3E2X7R2A223K080AA" FP-CGA3E2X7R2A223K080AA_0603-MFG 8229.01,3679.34 r90 bottom value=22nF (schematic designator C39)
C39_A4 "CGA3E2X7R2A223K080AA" FP-CGA3E2X7R2A223K080AA_0603-MFG 10549.24,3676.14 r90 bottom value=22nF (schematic designator C39)
C40_A1 "CGA3E2X7R2A223K080AA" FP-CGA3E2X7R2A223K080AA_0603-MFG 3597.31,3769.17 r90 bottom value=22nF (schematic designator C40)
C40_A2 "CGA3E2X7R2A223K080AA" FP-CGA3E2X7R2A223K080AA_0603-MFG 5892.33,3769.17 r90 bottom value=22nF (schematic designator C40)
C40_A3 "CGA3E2X7R2A223K080AA" FP-CGA3E2X7R2A223K080AA_0603-MFG 8228.93,3772.38 r90 bottom value=22nF (schematic designator C40)
C40_A4 "CGA3E2X7R2A223K080AA" FP-CGA3E2X7R2A223K080AA_0603-MFG 10549.16,3769.17 r90 bottom value=22nF (schematic designator C40)
C42_A1 "CGA3E2X7R2A223K080AA" FP-CGA3E2X7R2A223K080AA_0603-MFG 3542.97,3676.14 r90 bottom value=22nF (schematic designator C42)
C42_A2 "CGA3E2X7R2A223K080AA" FP-CGA3E2X7R2A223K080AA_0603-MFG 5837.99,3676.14 r90 bottom value=22nF (schematic designator C42)
C42_A3 "CGA3E2X7R2A223K080AA" FP-CGA3E2X7R2A223K080AA_0603-MFG 8174.58,3679.34 r90 bottom value=22nF (schematic designator C42)
C42_A4 "CGA3E2X7R2A223K080AA" FP-CGA3E2X7R2A223K080AA_0603-MFG 10494.81,3676.14 r90 bottom value=22nF (schematic designator C42)
C43_A1 "CGA3E2X7R2A223K080AA" FP-CGA3E2X7R2A223K080AA_0603-MFG 3542.68,3769.17 r90 bottom value=22nF (schematic designator C43)
C43_A2 "CGA3E2X7R2A223K080AA" FP-CGA3E2X7R2A223K080AA_0603-MFG 5837.69,3769.17 r90 bottom value=22nF (schematic designator C43)
C43_A3 "CGA3E2X7R2A223K080AA" FP-CGA3E2X7R2A223K080AA_0603-MFG 8174.29,3772.38 r90 bottom value=22nF (schematic designator C43)
C43_A4 "CGA3E2X7R2A223K080AA" FP-CGA3E2X7R2A223K080AA_0603-MFG 10494.52,3769.17 r90 bottom value=22nF (schematic designator C43)
C45_A1 "GCM155R71H472KA37D" 0402 3103.66,1743.6 r180 top value=4700pF (schematic designator C45)
C45_A2 "GCM155R71H472KA37D" 0402 5398.68,1743.6 r180 top value=4700pF (schematic designator C45)
C45_A3 "GCM155R71H472KA37D" 0402 7735.28,1746.8 r180 top value=4700pF (schematic designator C45)
C45_A4 "GCM155R71H472KA37D" 0402 10055.51,1743.6 r180 top value=4700pF (schematic designator C45)
C46_A1 "GCM188R71C474KA55D" 0603 3556.2,1158.09 r180 top value=0.47uF (schematic designator C46)
C46_A2 "GCM188R71C474KA55D" 0603 5851.22,1158.09 r180 top value=0.47uF (schematic designator C46)
C46_A3 "GCM188R71C474KA55D" 0603 8187.81,1161.3 r180 top value=0.47uF (schematic designator C46)
C46_A4 "GCM188R71C474KA55D" 0603 10508.04,1158.09 r180 top value=0.47uF (schematic designator C46)
C47_A1 "CGA3E2X7R2A223K080AA" FP-CGA3E2X7R2A223K080AA_0603-MFG 3434.3,3676.14 r90 bottom value=22nF (schematic designator C47)
C47_A2 "CGA3E2X7R2A223K080AA" FP-CGA3E2X7R2A223K080AA_0603-MFG 5729.31,3676.14 r90 bottom value=22nF (schematic designator C47)
C47_A3 "CGA3E2X7R2A223K080AA" FP-CGA3E2X7R2A223K080AA_0603-MFG 8065.91,3679.34 r90 bottom value=22nF (schematic designator C47)
C47_A4 "CGA3E2X7R2A223K080AA" FP-CGA3E2X7R2A223K080AA_0603-MFG 10386.14,3676.14 r90 bottom value=22nF (schematic designator C47)
C48_A1 "CGA3E2X7R2A223K080AA" FP-CGA3E2X7R2A223K080AA_0603-MFG 3433.41,3769.17 r90 bottom value=22nF (schematic designator C48)
C48_A2 "CGA3E2X7R2A223K080AA" FP-CGA3E2X7R2A223K080AA_0603-MFG 5728.42,3769.17 r90 bottom value=22nF (schematic designator C48)
C48_A3 "CGA3E2X7R2A223K080AA" FP-CGA3E2X7R2A223K080AA_0603-MFG 8065.02,3772.38 r90 bottom value=22nF (schematic designator C48)
C48_A4 "CGA3E2X7R2A223K080AA" FP-CGA3E2X7R2A223K080AA_0603-MFG 10385.25,3769.17 r90 bottom value=22nF (schematic designator C48)
C49_A1 "GCM155R71H472KA37D" 0402 3047.06,1693.04 r180 top value=4700pF (schematic designator C49)
C49_A2 "GCM155R71H472KA37D" 0402 5342.08,1693.04 r180 top value=4700pF (schematic designator C49)
C49_A3 "GCM155R71H472KA37D" 0402 7678.68,1696.25 r180 top value=4700pF (schematic designator C49)
C49_A4 "GCM155R71H472KA37D" 0402 9998.91,1693.04 r180 top value=4700pF (schematic designator C49)
C50_A1 "CGA3E2X7R2A223K080AA" FP-CGA3E2X7R2A223K080AA_0603-MFG 3379.68,3676.14 r90 bottom value=22nF (schematic designator C50)
C50_A2 "CGA3E2X7R2A223K080AA" FP-CGA3E2X7R2A223K080AA_0603-MFG 5674.7,3676.14 r90 bottom value=22nF (schematic designator C50)
C50_A3 "CGA3E2X7R2A223K080AA" FP-CGA3E2X7R2A223K080AA_0603-MFG 8011.29,3679.34 r90 bottom value=22nF (schematic designator C50)
C50_A4 "CGA3E2X7R2A223K080AA" FP-CGA3E2X7R2A223K080AA_0603-MFG 10331.52,3676.14 r90 bottom value=22nF (schematic designator C50)
C51_A1 "CGA3E2X7R2A223K080AA" FP-CGA3E2X7R2A223K080AA_0603-MFG 3378.77,3769.17 r90 bottom value=22nF (schematic designator C51)
C51_A2 "CGA3E2X7R2A223K080AA" FP-CGA3E2X7R2A223K080AA_0603-MFG 5673.79,3769.17 r90 bottom value=22nF (schematic designator C51)
C51_A3 "CGA3E2X7R2A223K080AA" FP-CGA3E2X7R2A223K080AA_0603-MFG 8010.39,3772.38 r90 bottom value=22nF (schematic designator C51)
C51_A4 "CGA3E2X7R2A223K080AA" FP-CGA3E2X7R2A223K080AA_0603-MFG 10330.62,3769.17 r90 bottom value=22nF (schematic designator C51)
C52_A1 "GCM155R71H104KE02D" 0402 3099.05,958.16 r0 bottom value=0.1uF (schematic designator C52)
C52_A2 "GCM155R71H104KE02D" 0402 5394.06,958.16 r0 bottom value=0.1uF (schematic designator C52)
C52_A3 "GCM155R71H104KE02D" 0402 7730.66,961.37 r0 bottom value=0.1uF (schematic designator C52)
C52_A4 "GCM155R71H104KE02D" 0402 10050.89,958.16 r0 bottom value=0.1uF (schematic designator C52)
C53_A1 "GCM155R71H104KE02D" 0402 2826.12,1376.3 r270 bottom value=0.1uF (schematic designator C53)
C53_A2 "GCM155R71H104KE02D" 0402 5121.14,1376.3 r270 bottom value=0.1uF (schematic designator C53)
C53_A3 "GCM155R71H104KE02D" 0402 7457.73,1379.51 r270 bottom value=0.1uF (schematic designator C53)
C53_A4 "GCM155R71H104KE02D" 0402 9777.96,1376.3 r270 bottom value=0.1uF (schematic designator C53)
C54_A1 "GCM155R71H104KE02D" 0402 3209.23,1744.01 r180 bottom value=0.1uF (schematic designator C54)
C54_A2 "GCM155R71H104KE02D" 0402 5504.24,1744.01 r180 bottom value=0.1uF (schematic designator C54)
C54_A3 "GCM155R71H104KE02D" 0402 7840.84,1747.22 r180 bottom value=0.1uF (schematic designator C54)
C54_A4 "GCM155R71H104KE02D" 0402 10161.07,1744.01 r180 bottom value=0.1uF (schematic designator C54)
C55_A1 "GCM188R71C105KA64D" 0603 3558.85,1093.83 r180 top value=1uF (schematic designator C55)
C55_A2 "GCM188R71C105KA64D" 0603 5853.86,1093.83 r180 top value=1uF (schematic designator C55)
C55_A3 "GCM188R71C105KA64D" 0603 8190.46,1097.03 r180 top value=1uF (schematic designator C55)
C55_A4 "GCM188R71C105KA64D" 0603 10510.69,1093.83 r180 top value=1uF (schematic designator C55)
C56_A1 "CGA3E2X7R2A223K080AA" FP-CGA3E2X7R2A223K080AA_0603-MFG 3325.25,3676.14 r90 bottom value=22nF (schematic designator C56)
C56_A2 "CGA3E2X7R2A223K080AA" FP-CGA3E2X7R2A223K080AA_0603-MFG 5620.27,3676.14 r90 bottom value=22nF (schematic designator C56)
C56_A3 "CGA3E2X7R2A223K080AA" FP-CGA3E2X7R2A223K080AA_0603-MFG 7956.86,3679.34 r90 bottom value=22nF (schematic designator C56)
C56_A4 "CGA3E2X7R2A223K080AA" FP-CGA3E2X7R2A223K080AA_0603-MFG 10277.09,3676.14 r90 bottom value=22nF (schematic designator C56)
C57_A1 "CGA3E2X7R2A223K080AA" FP-CGA3E2X7R2A223K080AA_0603-MFG 3324.14,3769.17 r90 bottom value=22nF (schematic designator C57)
C57_A2 "CGA3E2X7R2A223K080AA" FP-CGA3E2X7R2A223K080AA_0603-MFG 5619.16,3769.17 r90 bottom value=22nF (schematic designator C57)
C57_A3 "CGA3E2X7R2A223K080AA" FP-CGA3E2X7R2A223K080AA_0603-MFG 7955.75,3772.38 r90 bottom value=22nF (schematic designator C57)
C57_A4 "CGA3E2X7R2A223K080AA" FP-CGA3E2X7R2A223K080AA_0603-MFG 10275.98,3769.17 r90 bottom value=22nF (schematic designator C57)
C58_A1 "GCM155R71H472KA37D" 0402 2820.86,1496.42 r270 top value=4700pF (schematic designator C58)
C58_A2 "GCM155R71H472KA37D" 0402 5115.88,1496.42 r270 top value=4700pF (schematic designator C58)
C58_A3 "GCM155R71H472KA37D" 0402 7452.48,1499.63 r270 top value=4700pF (schematic designator C58)
C58_A4 "GCM155R71H472KA37D" 0402 9772.71,1496.42 r270 top value=4700pF (schematic designator C58)
C59_A1 "CGA3E2X7R2A223K080AA" FP-CGA3E2X7R2A223K080AA_0603-MFG 3270.82,3676.14 r90 bottom value=22nF (schematic designator C59)
C59_A2 "CGA3E2X7R2A223K080AA" FP-CGA3E2X7R2A223K080AA_0603-MFG 5565.84,3676.14 r90 bottom value=22nF (schematic designator C59)
C59_A3 "CGA3E2X7R2A223K080AA" FP-CGA3E2X7R2A223K080AA_0603-MFG 7902.43,3679.34 r90 bottom value=22nF (schematic designator C59)
C59_A4 "CGA3E2X7R2A223K080AA" FP-CGA3E2X7R2A223K080AA_0603-MFG 10222.66,3676.14 r90 bottom value=22nF (schematic designator C59)
C60_A1 "CGA3E2X7R2A223K080AA" FP-CGA3E2X7R2A223K080AA_0603-MFG 3269.51,3769.17 r90 bottom value=22nF (schematic designator C60)
C60_A2 "CGA3E2X7R2A223K080AA" FP-CGA3E2X7R2A223K080AA_0603-MFG 5564.52,3769.17 r90 bottom value=22nF (schematic designator C60)
C60_A3 "CGA3E2X7R2A223K080AA" FP-CGA3E2X7R2A223K080AA_0603-MFG 7901.12,3772.38 r90 bottom value=22nF (schematic designator C60)
C60_A4 "CGA3E2X7R2A223K080AA" FP-CGA3E2X7R2A223K080AA_0603-MFG 10221.35,3769.17 r90 bottom value=22nF (schematic designator C60)
C61_A1 "GCM155R71H472KA37D" 0402 3244.28,1556.77 r270 bottom value=4700pF (schematic designator C61)
C61_A2 "GCM155R71H472KA37D" 0402 5539.3,1556.77 r270 bottom value=4700pF (schematic designator C61)
C61_A3 "GCM155R71H472KA37D" 0402 7875.9,1559.98 r270 bottom value=4700pF (schematic designator C61)
C61_A4 "GCM155R71H472KA37D" 0402 10196.13,1556.77 r270 bottom value=4700pF (schematic designator C61)
C62_A1 "GCM155R71H104KE02D" 0402 3298.96,1556.77 r90 bottom value=0.1uF (schematic designator C62)
C62_A2 "GCM155R71H104KE02D" 0402 5593.97,1556.77 r90 bottom value=0.1uF (schematic designator C62)
C62_A3 "GCM155R71H104KE02D" 0402 7930.57,1559.98 r90 bottom value=0.1uF (schematic designator C62)
C62_A4 "GCM155R71H104KE02D" 0402 10250.8,1556.77 r90 bottom value=0.1uF (schematic designator C62)
C63_A1 "GCM155R71H472KA37D" 0402 2770.09,1432.95 r270 top value=4700pF (schematic designator C63)
C63_A2 "GCM155R71H472KA37D" 0402 5065.11,1432.95 r270 top value=4700pF (schematic designator C63)
C63_A3 "GCM155R71H472KA37D" 0402 7401.71,1436.16 r270 top value=4700pF (schematic designator C63)
C63_A4 "GCM155R71H472KA37D" 0402 9721.94,1432.95 r270 top value=4700pF (schematic designator C63)
C64_A1 "GCM188R71C474KA55D" 0603 3582.68,1259.84 r180 top value=0.47uF (schematic designator C64)
C64_A2 "GCM188R71C474KA55D" 0603 5877.69,1259.84 r180 top value=0.47uF (schematic designator C64)
C64_A3 "GCM188R71C474KA55D" 0603 8214.29,1263.05 r180 top value=0.47uF (schematic designator C64)
C64_A4 "GCM188R71C474KA55D" 0603 10534.52,1259.84 r180 top value=0.47uF (schematic designator C64)
C65_A1 "CGA3E2X7R2A223K080AA" FP-CGA3E2X7R2A223K080AA_0603-MFG 3216.39,3676.14 r90 bottom value=22nF (schematic designator C65)
C65_A2 "CGA3E2X7R2A223K080AA" FP-CGA3E2X7R2A223K080AA_0603-MFG 5511.41,3676.14 r90 bottom value=22nF (schematic designator C65)
C65_A3 "CGA3E2X7R2A223K080AA" FP-CGA3E2X7R2A223K080AA_0603-MFG 7848,3679.34 r90 bottom value=22nF (schematic designator C65)
C65_A4 "CGA3E2X7R2A223K080AA" FP-CGA3E2X7R2A223K080AA_0603-MFG 10168.23,3676.14 r90 bottom value=22nF (schematic designator C65)
C66_A1 "CGA3E2X7R2A223K080AA" FP-CGA3E2X7R2A223K080AA_0603-MFG 3214.87,3769.17 r90 bottom value=22nF (schematic designator C66)
C66_A2 "CGA3E2X7R2A223K080AA" FP-CGA3E2X7R2A223K080AA_0603-MFG 5509.89,3769.17 r90 bottom value=22nF (schematic designator C66)
C66_A3 "CGA3E2X7R2A223K080AA" FP-CGA3E2X7R2A223K080AA_0603-MFG 7846.48,3772.38 r90 bottom value=22nF (schematic designator C66)
C66_A4 "CGA3E2X7R2A223K080AA" FP-CGA3E2X7R2A223K080AA_0603-MFG 10166.71,3769.17 r90 bottom value=22nF (schematic designator C66)
C67_A1 "GCM155R71H472KA37D" 0402 3139.48,1557.6 r270 bottom value=4700pF (schematic designator C67)
C67_A2 "GCM155R71H472KA37D" 0402 5434.5,1557.6 r270 bottom value=4700pF (schematic designator C67)
C67_A3 "GCM155R71H472KA37D" 0402 7771.09,1560.8 r270 bottom value=4700pF (schematic designator C67)
C67_A4 "GCM155R71H472KA37D" 0402 10091.32,1557.6 r270 bottom value=4700pF (schematic designator C67)
C68_A1 "GCM155R71H104KE02D" 0402 3189.57,1557.75 r90 bottom value=0.1uF (schematic designator C68)
C68_A2 "GCM155R71H104KE02D" 0402 5484.59,1557.75 r90 bottom value=0.1uF (schematic designator C68)
C68_A3 "GCM155R71H104KE02D" 0402 7821.18,1560.96 r90 bottom value=0.1uF (schematic designator C68)
C68_A4 "GCM155R71H104KE02D" 0402 10141.41,1557.75 r90 bottom value=0.1uF (schematic designator C68)
C69_A1 "CGA3E2X7R2A223K080AA" FP-CGA3E2X7R2A223K080AA_0603-MFG 3161.96,3676.14 r90 bottom value=22nF (schematic designator C69)
C69_A2 "CGA3E2X7R2A223K080AA" FP-CGA3E2X7R2A223K080AA_0603-MFG 5456.97,3676.14 r90 bottom value=22nF (schematic designator C69)
C69_A3 "CGA3E2X7R2A223K080AA" FP-CGA3E2X7R2A223K080AA_0603-MFG 7793.57,3679.34 r90 bottom value=22nF (schematic designator C69)
C69_A4 "CGA3E2X7R2A223K080AA" FP-CGA3E2X7R2A223K080AA_0603-MFG 10113.8,3676.14 r90 bottom value=22nF (schematic designator C69)
C70_A1 "CGA3E2X7R2A223K080AA" FP-CGA3E2X7R2A223K080AA_0603-MFG 3160.24,3769.17 r90 bottom value=22nF (schematic designator C70)
C70_A2 "CGA3E2X7R2A223K080AA" FP-CGA3E2X7R2A223K080AA_0603-MFG 5455.25,3769.17 r90 bottom value=22nF (schematic designator C70)
C70_A3 "CGA3E2X7R2A223K080AA" FP-CGA3E2X7R2A223K080AA_0603-MFG 7791.85,3772.38 r90 bottom value=22nF (schematic designator C70)
C70_A4 "CGA3E2X7R2A223K080AA" FP-CGA3E2X7R2A223K080AA_0603-MFG 10112.08,3769.17 r90 bottom value=22nF (schematic designator C70)
C71_A1 "GCM155R71H472KA37D" 0402 2820.87,1378.98 r270 top value=4700pF (schematic designator C71)
C71_A2 "GCM155R71H472KA37D" 0402 5115.89,1378.98 r270 top value=4700pF (schematic designator C71)
C71_A3 "GCM155R71H472KA37D" 0402 7452.48,1382.19 r270 top value=4700pF (schematic designator C71)
C71_A4 "GCM155R71H472KA37D" 0402 9772.71,1378.98 r270 top value=4700pF (schematic designator C71)
C72_A1 "GCM155R71H104KE02D" 0402 3144.49,908.95 r0 bottom value=0.1uF (schematic designator C72)
C72_A2 "GCM155R71H104KE02D" 0402 5439.5,908.95 r0 bottom value=0.1uF (schematic designator C72)
C72_A3 "GCM155R71H104KE02D" 0402 7776.1,912.16 r0 bottom value=0.1uF (schematic designator C72)
C72_A4 "GCM155R71H104KE02D" 0402 10096.33,908.95 r0 bottom value=0.1uF (schematic designator C72)
C73_A1 "GCM155R71H104KE02D" 0402 2774.41,1309.22 r270 bottom value=0.1uF (schematic designator C73)
C73_A2 "GCM155R71H104KE02D" 0402 5069.43,1309.22 r270 bottom value=0.1uF (schematic designator C73)
C73_A3 "GCM155R71H104KE02D" 0402 7406.02,1312.43 r270 bottom value=0.1uF (schematic designator C73)
C73_A4 "GCM155R71H104KE02D" 0402 9726.25,1309.22 r270 bottom value=0.1uF (schematic designator C73)
C74_A1 "GCM155R71H104KE02D" 0402 3146.11,1690.24 r180 bottom value=0.1uF (schematic designator C74)
C74_A2 "GCM155R71H104KE02D" 0402 5441.12,1690.24 r180 bottom value=0.1uF (schematic designator C74)
C74_A3 "GCM155R71H104KE02D" 0402 7777.72,1693.45 r180 bottom value=0.1uF (schematic designator C74)
C74_A4 "GCM155R71H104KE02D" 0402 10097.95,1690.24 r180 bottom value=0.1uF (schematic designator C74)
C75_A1 "GCM155R71H472KA37D" 0402 3039.3,1556.77 r270 bottom value=4700pF (schematic designator C75)
C75_A2 "GCM155R71H472KA37D" 0402 5334.32,1556.77 r270 bottom value=4700pF (schematic designator C75)
C75_A3 "GCM155R71H472KA37D" 0402 7670.92,1559.98 r270 bottom value=4700pF (schematic designator C75)
C75_A4 "GCM155R71H472KA37D" 0402 9991.15,1556.77 r270 bottom value=4700pF (schematic designator C75)
C76_A1 "GCM155R71H104KE02D" 0402 3089.39,1556.77 r90 bottom value=0.1uF (schematic designator C76)
C76_A2 "GCM155R71H104KE02D" 0402 5384.41,1556.77 r90 bottom value=0.1uF (schematic designator C76)
C76_A3 "GCM155R71H104KE02D" 0402 7721.01,1559.98 r90 bottom value=0.1uF (schematic designator C76)
C76_A4 "GCM155R71H104KE02D" 0402 10041.24,1556.77 r90 bottom value=0.1uF (schematic designator C76)
C77_A1 "CGA3E2X7R2A223K080AA" FP-CGA3E2X7R2A223K080AA_0603-MFG 3107.53,3676.14 r90 bottom value=22nF (schematic designator C77)
C77_A2 "CGA3E2X7R2A223K080AA" FP-CGA3E2X7R2A223K080AA_0603-MFG 5402.54,3676.14 r90 bottom value=22nF (schematic designator C77)
C77_A3 "CGA3E2X7R2A223K080AA" FP-CGA3E2X7R2A223K080AA_0603-MFG 7739.14,3679.34 r90 bottom value=22nF (schematic designator C77)
C77_A4 "CGA3E2X7R2A223K080AA" FP-CGA3E2X7R2A223K080AA_0603-MFG 10059.37,3676.14 r90 bottom value=22nF (schematic designator C77)
C78_A1 "CGA3E2X7R2A223K080AA" FP-CGA3E2X7R2A223K080AA_0603-MFG 3105.6,3769.17 r90 bottom value=22nF (schematic designator C78)
C78_A2 "CGA3E2X7R2A223K080AA" FP-CGA3E2X7R2A223K080AA_0603-MFG 5400.62,3769.17 r90 bottom value=22nF (schematic designator C78)
C78_A3 "CGA3E2X7R2A223K080AA" FP-CGA3E2X7R2A223K080AA_0603-MFG 7737.21,3772.38 r90 bottom value=22nF (schematic designator C78)
C78_A4 "CGA3E2X7R2A223K080AA" FP-CGA3E2X7R2A223K080AA_0603-MFG 10057.44,3769.17 r90 bottom value=22nF (schematic designator C78)
C79_A1 "GCM155R71H472KA37D" 0402 2962.1,1512.36 r0 bottom value=4700pF (schematic designator C79)
C79_A2 "GCM155R71H472KA37D" 0402 5257.11,1512.36 r0 bottom value=4700pF (schematic designator C79)
C79_A3 "GCM155R71H472KA37D" 0402 7593.71,1515.57 r0 bottom value=4700pF (schematic designator C79)
C79_A4 "GCM155R71H472KA37D" 0402 9913.94,1512.36 r0 bottom value=4700pF (schematic designator C79)
C80_A1 "GCM155R71H104KE02D" 0402 2962.1,1564.96 r180 bottom value=0.1uF (schematic designator C80)
C80_A2 "GCM155R71H104KE02D" 0402 5257.11,1564.96 r180 bottom value=0.1uF (schematic designator C80)
C80_A3 "GCM155R71H104KE02D" 0402 7593.71,1568.17 r180 bottom value=0.1uF (schematic designator C80)
C80_A4 "GCM155R71H104KE02D" 0402 9913.94,1564.96 r180 bottom value=0.1uF (schematic designator C80)
C81_A1 "GCM155R71H472KA37D" 0402 2769.85,1326.19 r270 top value=4700pF (schematic designator C81)
C81_A2 "GCM155R71H472KA37D" 0402 5064.86,1326.19 r270 top value=4700pF (schematic designator C81)
C81_A3 "GCM155R71H472KA37D" 0402 7401.46,1329.4 r270 top value=4700pF (schematic designator C81)
C81_A4 "GCM155R71H472KA37D" 0402 9721.69,1326.19 r270 top value=4700pF (schematic designator C81)
C82_A1 "CGA3E2X7R2A223K080AA" FP-CGA3E2X7R2A223K080AA_0603-MFG 3053.1,3676.14 r90 bottom value=22nF (schematic designator C82)
C82_A2 "CGA3E2X7R2A223K080AA" FP-CGA3E2X7R2A223K080AA_0603-MFG 5348.11,3676.14 r90 bottom value=22nF (schematic designator C82)
C82_A3 "CGA3E2X7R2A223K080AA" FP-CGA3E2X7R2A223K080AA_0603-MFG 7684.71,3679.34 r90 bottom value=22nF (schematic designator C82)
C82_A4 "CGA3E2X7R2A223K080AA" FP-CGA3E2X7R2A223K080AA_0603-MFG 10004.94,3676.14 r90 bottom value=22nF (schematic designator C82)
C83_A1 "CGA3E2X7R2A223K080AA" FP-CGA3E2X7R2A223K080AA_0603-MFG 3050.97,3769.17 r90 bottom value=22nF (schematic designator C83)
C83_A2 "CGA3E2X7R2A223K080AA" FP-CGA3E2X7R2A223K080AA_0603-MFG 5345.98,3769.17 r90 bottom value=22nF (schematic designator C83)
C83_A3 "CGA3E2X7R2A223K080AA" FP-CGA3E2X7R2A223K080AA_0603-MFG 7682.58,3772.38 r90 bottom value=22nF (schematic designator C83)
C83_A4 "CGA3E2X7R2A223K080AA" FP-CGA3E2X7R2A223K080AA_0603-MFG 10002.81,3769.17 r90 bottom value=22nF (schematic designator C83)
C84_A1 "GCM155R71H472KA37D" 0402 2962.1,1407.17 r0 bottom value=4700pF (schematic designator C84)
C84_A2 "GCM155R71H472KA37D" 0402 5257.11,1407.17 r0 bottom value=4700pF (schematic designator C84)
C84_A3 "GCM155R71H472KA37D" 0402 7593.71,1410.38 r0 bottom value=4700pF (schematic designator C84)
C84_A4 "GCM155R71H472KA37D" 0402 9913.94,1407.17 r0 bottom value=4700pF (schematic designator C84)
C85_A1 "GCM155R71H104KE02D" 0402 2962.1,1459.77 r180 bottom value=0.1uF (schematic designator C85)
C85_A2 "GCM155R71H104KE02D" 0402 5257.11,1459.77 r180 bottom value=0.1uF (schematic designator C85)
C85_A3 "GCM155R71H104KE02D" 0402 7593.71,1462.97 r180 bottom value=0.1uF (schematic designator C85)
C85_A4 "GCM155R71H104KE02D" 0402 9913.94,1459.77 r180 bottom value=0.1uF (schematic designator C85)
C86_A1 "CGA3E2X7R2A223K080AA" FP-CGA3E2X7R2A223K080AA_0603-MFG 2998.67,3676.14 r90 bottom value=22nF (schematic designator C86)
C86_A2 "CGA3E2X7R2A223K080AA" FP-CGA3E2X7R2A223K080AA_0603-MFG 5293.68,3676.14 r90 bottom value=22nF (schematic designator C86)
C86_A3 "CGA3E2X7R2A223K080AA" FP-CGA3E2X7R2A223K080AA_0603-MFG 7630.28,3679.34 r90 bottom value=22nF (schematic designator C86)
C86_A4 "CGA3E2X7R2A223K080AA" FP-CGA3E2X7R2A223K080AA_0603-MFG 9950.51,3676.14 r90 bottom value=22nF (schematic designator C86)
C87_A1 "CGA3E2X7R2A223K080AA" FP-CGA3E2X7R2A223K080AA_0603-MFG 2996.33,3769.17 r90 bottom value=22nF (schematic designator C87)
C87_A2 "CGA3E2X7R2A223K080AA" FP-CGA3E2X7R2A223K080AA_0603-MFG 5291.35,3769.17 r90 bottom value=22nF (schematic designator C87)
C87_A3 "CGA3E2X7R2A223K080AA" FP-CGA3E2X7R2A223K080AA_0603-MFG 7627.94,3772.38 r90 bottom value=22nF (schematic designator C87)
C87_A4 "CGA3E2X7R2A223K080AA" FP-CGA3E2X7R2A223K080AA_0603-MFG 9948.17,3769.17 r90 bottom value=22nF (schematic designator C87)
C88_A1 "GCM155R71H472KA37D" 0402 2821.79,1261.53 r270 top value=4700pF (schematic designator C88)
C88_A2 "GCM155R71H472KA37D" 0402 5116.8,1261.53 r270 top value=4700pF (schematic designator C88)
C88_A3 "GCM155R71H472KA37D" 0402 7453.4,1264.74 r270 top value=4700pF (schematic designator C88)
C88_A4 "GCM155R71H472KA37D" 0402 9773.63,1261.53 r270 top value=4700pF (schematic designator C88)
C89_A1 "GCM155R71H472KA37D" 0402 2962.1,1301.98 r0 bottom value=4700pF (schematic designator C89)
C89_A2 "GCM155R71H472KA37D" 0402 5257.11,1301.98 r0 bottom value=4700pF (schematic designator C89)
C89_A3 "GCM155R71H472KA37D" 0402 7593.71,1305.18 r0 bottom value=4700pF (schematic designator C89)
C89_A4 "GCM155R71H472KA37D" 0402 9913.94,1301.98 r0 bottom value=4700pF (schematic designator C89)
C90_A1 "GCM155R71H104KE02D" 0402 2962.1,1354.57 r180 bottom value=0.1uF (schematic designator C90)
C90_A2 "GCM155R71H104KE02D" 0402 5257.11,1354.57 r180 bottom value=0.1uF (schematic designator C90)
C90_A3 "GCM155R71H104KE02D" 0402 7593.71,1357.78 r180 bottom value=0.1uF (schematic designator C90)
C90_A4 "GCM155R71H104KE02D" 0402 9913.94,1354.57 r180 bottom value=0.1uF (schematic designator C90)
C91_A1 "CGA3E2X7R2A223K080AA" FP-CGA3E2X7R2A223K080AA_0603-MFG 2944.24,3676.14 r90 bottom value=22nF (schematic designator C91)
C91_A2 "CGA3E2X7R2A223K080AA" FP-CGA3E2X7R2A223K080AA_0603-MFG 5239.25,3676.14 r90 bottom value=22nF (schematic designator C91)
C91_A3 "CGA3E2X7R2A223K080AA" FP-CGA3E2X7R2A223K080AA_0603-MFG 7575.85,3679.34 r90 bottom value=22nF (schematic designator C91)
C91_A4 "CGA3E2X7R2A223K080AA" FP-CGA3E2X7R2A223K080AA_0603-MFG 9896.08,3676.14 r90 bottom value=22nF (schematic designator C91)
C92_A1 "CGA3E2X7R2A223K080AA" FP-CGA3E2X7R2A223K080AA_0603-MFG 2941.7,3771.14 r90 bottom value=22nF (schematic designator C92)
C92_A2 "CGA3E2X7R2A223K080AA" FP-CGA3E2X7R2A223K080AA_0603-MFG 5236.71,3771.14 r90 bottom value=22nF (schematic designator C92)
C92_A3 "CGA3E2X7R2A223K080AA" FP-CGA3E2X7R2A223K080AA_0603-MFG 7573.31,3774.35 r90 bottom value=22nF (schematic designator C92)
C92_A4 "CGA3E2X7R2A223K080AA" FP-CGA3E2X7R2A223K080AA_0603-MFG 9893.54,3771.14 r90 bottom value=22nF (schematic designator C92)
C93_A1 "GCM155R71H104KE02D" 0402 3203.59,958.16 r0 bottom value=0.1uF (schematic designator C93)
C93_A2 "GCM155R71H104KE02D" 0402 5498.61,958.16 r0 bottom value=0.1uF (schematic designator C93)
C93_A3 "GCM155R71H104KE02D" 0402 7835.21,961.37 r0 bottom value=0.1uF (schematic designator C93)
C93_A4 "GCM155R71H104KE02D" 0402 10155.44,958.16 r0 bottom value=0.1uF (schematic designator C93)
C94_A1 "GCM155R71H104KE02D" 0402 2826.12,1265.28 r270 bottom value=0.1uF (schematic designator C94)
C94_A2 "GCM155R71H104KE02D" 0402 5121.14,1265.28 r270 bottom value=0.1uF (schematic designator C94)
C94_A3 "GCM155R71H104KE02D" 0402 7457.73,1268.49 r270 bottom value=0.1uF (schematic designator C94)
C94_A4 "GCM155R71H104KE02D" 0402 9777.96,1265.28 r270 bottom value=0.1uF (schematic designator C94)
C95_A1 "GCM155R71H104KE02D" 0402 3101.11,1744.01 r180 bottom value=0.1uF (schematic designator C95)
C95_A2 "GCM155R71H104KE02D" 0402 5396.12,1744.01 r180 bottom value=0.1uF (schematic designator C95)
C95_A3 "GCM155R71H104KE02D" 0402 7732.72,1747.22 r180 bottom value=0.1uF (schematic designator C95)
C95_A4 "GCM155R71H104KE02D" 0402 10052.95,1744.01 r180 bottom value=0.1uF (schematic designator C95)
C96_A1 "GCM155R71H472KA37D" 0402 2962.1,1196.78 r0 bottom value=4700pF (schematic designator C96)
C96_A2 "GCM155R71H472KA37D" 0402 5257.11,1196.78 r0 bottom value=4700pF (schematic designator C96)
C96_A3 "GCM155R71H472KA37D" 0402 7593.71,1199.99 r0 bottom value=4700pF (schematic designator C96)
C96_A4 "GCM155R71H472KA37D" 0402 9913.94,1196.78 r0 bottom value=4700pF (schematic designator C96)
C97_A1 "GCM155R71H104KE02D" 0402 2962.1,1249.38 r180 bottom value=0.1uF (schematic designator C97)
C97_A2 "GCM155R71H104KE02D" 0402 5257.11,1249.38 r180 bottom value=0.1uF (schematic designator C97)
